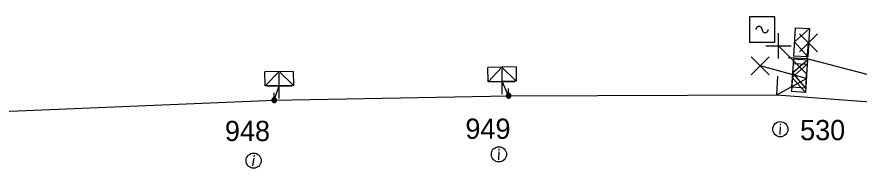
# Model space of a CAD drawing. Extents: x -540466 to -537383, y -1184038 to -1179972.
# Drawn here: x -538225.36 to -538183.68, y -1180266.48 to -1180258.86 of the extents above; entities that cross this region are included whole.
import ezdxf

# ---------------------------------------------------------------- set-up
doc = ezdxf.new("R2010")
doc.units = 0
for name, color, linetype in [('Vrstva 1', 7, 'Continuous'), ('Vrstva 10', 7, 'Continuous'), ('Vrstva 13', 7, 'Continuous'), ('Vrstva 14', 7, 'Continuous'), ('Vrstva 2', 7, 'Continuous'), ('Vrstva 31', 7, 'Continuous'), ('Vrstva 34', 7, 'Continuous'), ('Vrstva 36', 7, 'Continuous'), ('Vrstva 50', 7, 'Continuous'), ('Vrstva 54', 7, 'Continuous'), ('Vrstva 59', 7, 'Continuous'), ('Vrstva 8', 7, 'Continuous'), ('Vrstva 9', 7, 'Continuous')]:
    doc.layers.add(name, color=color, linetype=linetype)

# ---------------------------------------------------------------- blocks, each defined once
blk = doc.blocks.new('NN770')
at = {"layer": 'Vrstva 10'}
for p, q in [((0.002, 0.187), (0.002, 0.263)), ((0.002, -0.276), (0.002, 0.111))]:
    blk.add_line(p, q, dxfattribs=at)
blk.add_circle((0, -0.008), 0.375, dxfattribs=at)
blk = doc.blocks.new('NN800')
at = {"layer": 'Vrstva 1'}
for points in [[(-0.442, 0.442), (0.442, -0.442)], [(-0.442, -0.442), (0.442, 0.442)]]:
    blk.add_lwpolyline(points, dxfattribs=at)
blk = doc.blocks.new('NN630')
at = {"layer": 'Vrstva 9'}
for points in [[(-0.003, -0.7), (-0.703, 0)], [(-0.703, -0.7), (-0.703, 0), (0.697, 0), (0.697, -0.7)], [(-0.003, -0.7), (0.697, 0)], [(-0.703, -0.7), (0.697, -0.7)]]:
    blk.add_lwpolyline(points, dxfattribs=at)
blk = doc.blocks.new('NN740')
at = {"layer": 'Vrstva 1'}
for points in [[(0.624, 0.624), (-0.626, 0.624)], [(-0.626, 0.624), (-0.626, -0.626)], [(0.624, -0.626), (0.624, 0.624)], [(-0.001, -0.001), (-0.002, 0.015), (-0.004, 0.031), (-0.008, 0.046), (-0.014, 0.061), (-0.021, 0.075), (-0.03, 0.089), (-0.04, 0.101), (-0.051, 0.112), (-0.063, 0.123), (-0.077, 0.131), (-0.091, 0.139), (-0.106, 0.145), (-0.121, 0.149), (-0.137, 0.151), (-0.153, 0.152), (-0.169, 0.151), (-0.185, 0.149), (-0.2, 0.145), (-0.215, 0.139), (-0.229, 0.132), (-0.243, 0.123), (-0.255, 0.113), (-0.266, 0.102), (-0.276, 0.09), (-0.285, 0.076), (-0.293, 0.062), (-0.298, 0.047), (-0.303, 0.032), (-0.305, 0.016), (-0.306, 0), (-0.306, -0.001)], [(-0.001, -0.001), (0, -0.017), (0.002, -0.032), (0.006, -0.048), (0.011, -0.062), (0.018, -0.077), (0.026, -0.09), (0.036, -0.102), (0.047, -0.114), (0.059, -0.124), (0.072, -0.133), (0.085, -0.14), (0.1, -0.146), (0.115, -0.15), (0.131, -0.153), (0.146, -0.154), (0.162, -0.154), (0.178, -0.151), (0.193, -0.148), (0.208, -0.142), (0.222, -0.135), (0.235, -0.127), (0.247, -0.118), (0.259, -0.107), (0.269, -0.095), (0.278, -0.082), (0.285, -0.068), (0.291, -0.053), (0.295, -0.038), (0.298, -0.023), (0.299, -0.007), (0.299, -0.006)], [(-0.626, -0.626), (0.624, -0.626)]]:
    blk.add_lwpolyline(points, dxfattribs=at)
blk = doc.blocks.new('NN500')
at = {"layer": 'Vrstva 2'}
for points in [[(-0.001, -0.235), (0.023, -0.234), (0.048, -0.23), (0.071, -0.224), (0.094, -0.215), (0.116, -0.204), (0.137, -0.191), (0.156, -0.175), (0.173, -0.158), (0.189, -0.139), (0.202, -0.118), (0.213, -0.096), (0.222, -0.073), (0.229, -0.049), (0.232, -0.025), (0.234, 0), (0.232, 0.024), (0.229, 0.048), (0.222, 0.072), (0.213, 0.095), (0.202, 0.117), (0.189, 0.138), (0.173, 0.157), (0.156, 0.174), (0.137, 0.19), (0.116, 0.203), (0.094, 0.214), (0.071, 0.223), (0.048, 0.229), (0.023, 0.233), (-0.001, 0.235), (-0.026, 0.233), (-0.05, 0.229), (-0.074, 0.223), (-0.097, 0.214), (-0.119, 0.203), (-0.139, 0.19), (-0.158, 0.174), (-0.176, 0.157), (-0.191, 0.138), (-0.205, 0.117), (-0.216, 0.095), (-0.225, 0.072), (-0.231, 0.048), (-0.235, 0.024), (-0.236, 0), (-0.235, -0.025), (-0.231, -0.049), (-0.225, -0.073), (-0.216, -0.096), (-0.205, -0.118), (-0.191, -0.139), (-0.176, -0.158), (-0.158, -0.175), (-0.139, -0.191), (-0.119, -0.204), (-0.097, -0.215), (-0.074, -0.224), (-0.05, -0.23), (-0.026, -0.234), (-0.001, -0.235)], [(-0.001, -0.235), (0.023, -0.234), (0.048, -0.23), (0.071, -0.224), (0.094, -0.215), (0.116, -0.204), (0.137, -0.191), (0.156, -0.175), (0.173, -0.158), (0.189, -0.139), (0.202, -0.118), (0.213, -0.096), (0.222, -0.073), (0.229, -0.049), (0.232, -0.025), (0.234, 0), (0.232, 0.024), (0.229, 0.048), (0.222, 0.072), (0.213, 0.095), (0.202, 0.117), (0.189, 0.138), (0.173, 0.157), (0.156, 0.174), (0.137, 0.19), (0.116, 0.203), (0.094, 0.214), (0.071, 0.223), (0.048, 0.229), (0.023, 0.233), (-0.001, 0.235), (-0.026, 0.233), (-0.05, 0.229), (-0.074, 0.223), (-0.097, 0.214), (-0.119, 0.203), (-0.139, 0.19), (-0.158, 0.174), (-0.176, 0.157), (-0.191, 0.138), (-0.205, 0.117), (-0.216, 0.095), (-0.225, 0.072), (-0.231, 0.048), (-0.235, 0.024), (-0.236, 0), (-0.235, -0.025), (-0.231, -0.049), (-0.225, -0.073), (-0.216, -0.096), (-0.205, -0.118), (-0.191, -0.139), (-0.176, -0.158), (-0.158, -0.175), (-0.139, -0.191), (-0.119, -0.204), (-0.097, -0.215), (-0.074, -0.224), (-0.05, -0.23), (-0.026, -0.234), (-0.001, -0.235)], [(-0.001, -0.206), (0.02, -0.205), (0.041, -0.201), (0.062, -0.196), (0.082, -0.188), (0.101, -0.178), (0.12, -0.167), (0.136, -0.153), (0.151, -0.138), (0.165, -0.121), (0.177, -0.103), (0.186, -0.084), (0.194, -0.064), (0.2, -0.043), (0.203, -0.022), (0.204, 0), (0.203, 0.021), (0.2, 0.042), (0.194, 0.063), (0.186, 0.083), (0.177, 0.102), (0.165, 0.12), (0.151, 0.137), (0.136, 0.152), (0.12, 0.166), (0.101, 0.177), (0.082, 0.187), (0.062, 0.195), (0.041, 0.2), (0.02, 0.204), (-0.001, 0.205), (-0.023, 0.204), (-0.044, 0.2), (-0.065, 0.195), (-0.085, 0.187), (-0.104, 0.177), (-0.122, 0.166), (-0.139, 0.152), (-0.154, 0.137), (-0.167, 0.12), (-0.179, 0.102), (-0.189, 0.083), (-0.197, 0.063), (-0.202, 0.042), (-0.205, 0.021), (-0.207, 0), (-0.205, -0.022), (-0.202, -0.043), (-0.197, -0.064), (-0.189, -0.084), (-0.179, -0.103), (-0.167, -0.121), (-0.154, -0.138), (-0.139, -0.153), (-0.122, -0.167), (-0.104, -0.178), (-0.085, -0.188), (-0.065, -0.196), (-0.044, -0.201), (-0.023, -0.205), (-0.001, -0.206)], [(-0.001, -0.176), (0.017, -0.175), (0.035, -0.172), (0.053, -0.168), (0.07, -0.161), (0.087, -0.153), (0.102, -0.143), (0.116, -0.131), (0.129, -0.118), (0.141, -0.104), (0.151, -0.088), (0.159, -0.072), (0.166, -0.055), (0.171, -0.037), (0.174, -0.019), (0.175, 0), (0.174, 0.018), (0.171, 0.036), (0.166, 0.054), (0.159, 0.071), (0.151, 0.087), (0.141, 0.103), (0.129, 0.117), (0.116, 0.13), (0.102, 0.142), (0.087, 0.152), (0.07, 0.16), (0.053, 0.167), (0.035, 0.172), (0.017, 0.174), (-0.001, 0.175), (-0.02, 0.174), (-0.038, 0.172), (-0.056, 0.167), (-0.073, 0.16), (-0.089, 0.152), (-0.105, 0.142), (-0.119, 0.13), (-0.132, 0.117), (-0.143, 0.103), (-0.153, 0.087), (-0.162, 0.071), (-0.168, 0.054), (-0.173, 0.036), (-0.176, 0.018), (-0.177, 0), (-0.176, -0.019), (-0.173, -0.037), (-0.168, -0.055), (-0.162, -0.072), (-0.153, -0.088), (-0.143, -0.104), (-0.132, -0.118), (-0.119, -0.131), (-0.105, -0.143), (-0.089, -0.153), (-0.073, -0.161), (-0.056, -0.168), (-0.038, -0.172), (-0.02, -0.175), (-0.001, -0.176)], [(-0.001, -0.147), (0.014, -0.146), (0.029, -0.143), (0.044, -0.139), (0.058, -0.134), (0.072, -0.127), (0.085, -0.119), (0.097, -0.109), (0.107, -0.098), (0.117, -0.086), (0.125, -0.073), (0.132, -0.06), (0.138, -0.046), (0.142, -0.031), (0.144, -0.016), (0.145, 0), (0.144, 0.015), (0.142, 0.03), (0.138, 0.045), (0.132, 0.059), (0.125, 0.073), (0.117, 0.086), (0.107, 0.097), (0.097, 0.108), (0.085, 0.118), (0.072, 0.126), (0.058, 0.133), (0.044, 0.139), (0.029, 0.143), (0.014, 0.145), (-0.001, 0.146), (-0.017, 0.145), (-0.032, 0.143), (-0.046, 0.139), (-0.061, 0.133), (-0.074, 0.126), (-0.087, 0.118), (-0.099, 0.108), (-0.11, 0.097), (-0.119, 0.086), (-0.128, 0.073), (-0.135, 0.059), (-0.14, 0.045), (-0.144, 0.03), (-0.147, 0.015), (-0.147, 0), (-0.147, -0.016), (-0.144, -0.031), (-0.14, -0.046), (-0.135, -0.06), (-0.128, -0.073), (-0.119, -0.086), (-0.11, -0.098), (-0.099, -0.109), (-0.087, -0.119), (-0.074, -0.127), (-0.061, -0.134), (-0.046, -0.139), (-0.032, -0.143), (-0.017, -0.146), (-0.001, -0.147)], [(-0.001, -0.117), (0.011, -0.116), (0.023, -0.114), (0.035, -0.111), (0.046, -0.107), (0.057, -0.101), (0.067, -0.095), (0.077, -0.087), (0.085, -0.078), (0.093, -0.069), (0.1, -0.059), (0.105, -0.048), (0.11, -0.036), (0.113, -0.025), (0.115, -0.013), (0.115, 0), (0.115, 0.012), (0.113, 0.024), (0.11, 0.036), (0.105, 0.047), (0.1, 0.058), (0.093, 0.068), (0.085, 0.078), (0.077, 0.086), (0.067, 0.094), (0.057, 0.101), (0.046, 0.106), (0.035, 0.11), (0.023, 0.114), (0.011, 0.116), (-0.001, 0.116), (-0.013, 0.116), (-0.025, 0.114), (-0.037, 0.11), (-0.049, 0.106), (-0.059, 0.101), (-0.07, 0.094), (-0.079, 0.086), (-0.088, 0.078), (-0.096, 0.068), (-0.102, 0.058), (-0.108, 0.047), (-0.112, 0.036), (-0.115, 0.024), (-0.117, 0.012), (-0.118, 0), (-0.117, -0.013), (-0.115, -0.025), (-0.112, -0.036), (-0.108, -0.048), (-0.102, -0.059), (-0.096, -0.069), (-0.088, -0.078), (-0.079, -0.087), (-0.07, -0.095), (-0.059, -0.101), (-0.049, -0.107), (-0.037, -0.111), (-0.025, -0.114), (-0.013, -0.116), (-0.001, -0.117)], [(-0.001, -0.087), (0.008, -0.087), (0.017, -0.085), (0.026, -0.083), (0.034, -0.08), (0.042, -0.076), (0.05, -0.071), (0.057, -0.065), (0.063, -0.059), (0.069, -0.051), (0.074, -0.044), (0.078, -0.036), (0.081, -0.027), (0.084, -0.019), (0.085, -0.01), (0.086, 0), (0.085, 0.009), (0.084, 0.018), (0.081, 0.026), (0.078, 0.035), (0.074, 0.043), (0.069, 0.051), (0.063, 0.058), (0.057, 0.064), (0.05, 0.07), (0.042, 0.075), (0.034, 0.079), (0.026, 0.082), (0.017, 0.085), (0.008, 0.086), (-0.001, 0.087), (-0.01, 0.086), (-0.019, 0.085), (-0.028, 0.082), (-0.037, 0.079), (-0.045, 0.075), (-0.052, 0.07), (-0.059, 0.064), (-0.066, 0.058), (-0.072, 0.051), (-0.077, 0.043), (-0.081, 0.035), (-0.084, 0.026), (-0.086, 0.018), (-0.088, 0.009), (-0.088, 0), (-0.088, -0.01), (-0.086, -0.019), (-0.084, -0.027), (-0.081, -0.036), (-0.077, -0.044), (-0.072, -0.052), (-0.066, -0.059), (-0.059, -0.065), (-0.052, -0.071), (-0.045, -0.076), (-0.037, -0.08), (-0.028, -0.083), (-0.019, -0.085), (-0.01, -0.087), (-0.001, -0.087)], [(-0.001, -0.058), (0.005, -0.057), (0.011, -0.056), (0.016, -0.055), (0.022, -0.053), (0.027, -0.05), (0.032, -0.047), (0.037, -0.043), (0.041, -0.039), (0.045, -0.034), (0.048, -0.029), (0.051, -0.024), (0.053, -0.018), (0.055, -0.012), (0.056, -0.006), (0.056, 0), (0.056, 0.006), (0.055, 0.011), (0.053, 0.017), (0.051, 0.023), (0.048, 0.028), (0.045, 0.033), (0.041, 0.038), (0.037, 0.042), (0.032, 0.046), (0.027, 0.049), (0.022, 0.052), (0.016, 0.054), (0.011, 0.056), (0.005, 0.057), (-0.001, 0.057), (-0.007, 0.057), (-0.013, 0.056), (-0.019, 0.054), (-0.025, 0.052), (-0.03, 0.049), (-0.035, 0.046), (-0.04, 0.042), (-0.044, 0.038), (-0.048, 0.033), (-0.051, 0.028), (-0.054, 0.023), (-0.056, 0.017), (-0.057, 0.011), (-0.058, 0.006), (-0.059, 0), (-0.058, -0.006), (-0.057, -0.012), (-0.056, -0.018), (-0.054, -0.024), (-0.051, -0.029), (-0.048, -0.034), (-0.044, -0.039), (-0.04, -0.043), (-0.035, -0.047), (-0.03, -0.05), (-0.025, -0.053), (-0.019, -0.055), (-0.013, -0.056), (-0.007, -0.057), (-0.001, -0.058)], [(-0.001, -0.028), (0.002, -0.028), (0.005, -0.028), (0.007, -0.027), (0.01, -0.026), (0.013, -0.024), (0.015, -0.023), (0.017, -0.021), (0.019, -0.019), (0.021, -0.017), (0.023, -0.014), (0.024, -0.012), (0.025, -0.009), (0.026, -0.006), (0.026, -0.003), (0.027, 0), (0.026, 0.002), (0.026, 0.005), (0.025, 0.008), (0.024, 0.011), (0.023, 0.013), (0.021, 0.016), (0.019, 0.018), (0.017, 0.02), (0.015, 0.022), (0.013, 0.024), (0.01, 0.025), (0.007, 0.026), (0.005, 0.027), (0.002, 0.027), (-0.001, 0.027), (-0.004, 0.027), (-0.007, 0.027), (-0.01, 0.026), (-0.012, 0.025), (-0.015, 0.024), (-0.018, 0.022), (-0.02, 0.02), (-0.022, 0.018), (-0.024, 0.016), (-0.025, 0.013), (-0.027, 0.011), (-0.028, 0.008), (-0.028, 0.005), (-0.029, 0.002), (-0.029, 0), (-0.029, -0.003), (-0.028, -0.006), (-0.028, -0.009), (-0.027, -0.012), (-0.025, -0.014), (-0.024, -0.017), (-0.022, -0.019), (-0.02, -0.021), (-0.018, -0.023), (-0.015, -0.024), (-0.012, -0.026), (-0.01, -0.027), (-0.007, -0.028), (-0.004, -0.028), (-0.001, -0.028)], [(0.234, 0), (0.704, 0)]]:
    blk.add_lwpolyline(points, dxfattribs=at)
blk = doc.blocks.new('NN510')
at = {"layer": 'Vrstva 2'}
blk.add_lwpolyline([(0.001, 0.002), (0.001, 0.939)], dxfattribs=at)

msp = doc.modelspace()

# ---------------------------------------------------------------- linework, layer by layer
at = {"layer": 'Vrstva 50'}
msp.add_lwpolyline([(-538256.78, -1180266.48), (-538245.796, -1180264.135), (-538234.046, -1180263.871), (-538212.623, -1180262.971), (-538201.026, -1180262.753), (-538187.757, -1180262.719), (-538176.097, -1180263.579), (-538159.437, -1180262.719), (-538138.61, -1180263.82)], dxfattribs=at)
at = {"layer": 'Vrstva 54'}
for points in [[(-538176.097, -1180263.579), (-538186.257, -1180260.929), (-538186.187, -1180260.144)], [(-538187.757, -1180262.719), (-538186.294, -1180261.901)]]:
    msp.add_lwpolyline(points, dxfattribs=at)
at = {"layer": 'Vrstva 59'}
for points in [[(-538186.294, -1180261.901), (-538186.288, -1180261.679), (-538187.669, -1180260.293)], [(-538186.294, -1180261.901), (-538188.578, -1180261.28)]]:
    msp.add_lwpolyline(points, dxfattribs=at)
at = {"layer": 'Vrstva 8'}
for points in [[(-538201.026, -1180262.753), (-538201.35, -1180262.05)], [(-538212.623, -1180262.971), (-538212.38, -1180262.26)]]:
    msp.add_lwpolyline(points, dxfattribs=at)

# ---------------------------------------------------------------- block references
at = {"layer": 'Vrstva 13'}
for p, rotation in [((-538186.257, -1180260.929), 87.25945770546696), ((-538187.757, -1180262.719), -3.4360110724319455)]:
    msp.add_blockref('NN510', p, dxfattribs=dict(at, rotation=rotation))
at = {"layer": 'Vrstva 13', "xscale": 0.5000000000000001}
for p, yscale, rotation in [((-538201.026, -1180262.753), 0.5, 91.15600003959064), ((-538212.623, -1180262.971), 0.4999999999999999, 90.7639999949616)]:
    msp.add_blockref('NN500', p, dxfattribs=dict(at, yscale=yscale, rotation=rotation))
at = {"layer": 'Vrstva 31'}
for p, rotation in [((-538186.187, -1180260.144), -93.59369721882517), ((-538186.294, -1180261.901), -93.59304440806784), ((-538186.288, -1180261.679), -94.00542051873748), ((-538212.38, -1180262.26), -179.23610267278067), ((-538201.35, -1180262.05), -178.8435388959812)]:
    msp.add_blockref('NN630', p, dxfattribs=dict(at, rotation=rotation))
at = {"layer": 'Vrstva 34'}
for name, p in [('NN740', (-538188.484, -1180259.484)), ('NN800', (-538186.187, -1180260.144)), ('NN800', (-538188.578, -1180261.28))]:
    msp.add_blockref(name, p, dxfattribs=at)
at = {"layer": 'Vrstva 34', "rotation": 45}
for p in [(-538187.669, -1180260.293), (-538212.38, -1180262.26), (-538201.35, -1180262.05)]:
    msp.add_blockref('NN800', p, dxfattribs=at)
at = {"layer": 'Vrstva 36'}
for p, rotation in [((-538187.583, -1180264.403), -3.436010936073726), ((-538201.506, -1180265.643), -2.2906110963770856), ((-538213.641, -1180265.954), -9.462322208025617)]:
    msp.add_blockref('NN770', p, dxfattribs=dict(at, rotation=rotation))

# ---------------------------------------------------------------- texts
at = {"layer": 'Vrstva 14'}
for s, p in [('948', (-538215.064, -1180264.994)), ('949', (-538203.164, -1180264.884)), ('530', (-538186.606, -1180264.952))]:
    msp.add_text(s, height=1, dxfattribs=at).set_placement(p)

doc.saveas('drawing.dxf')
